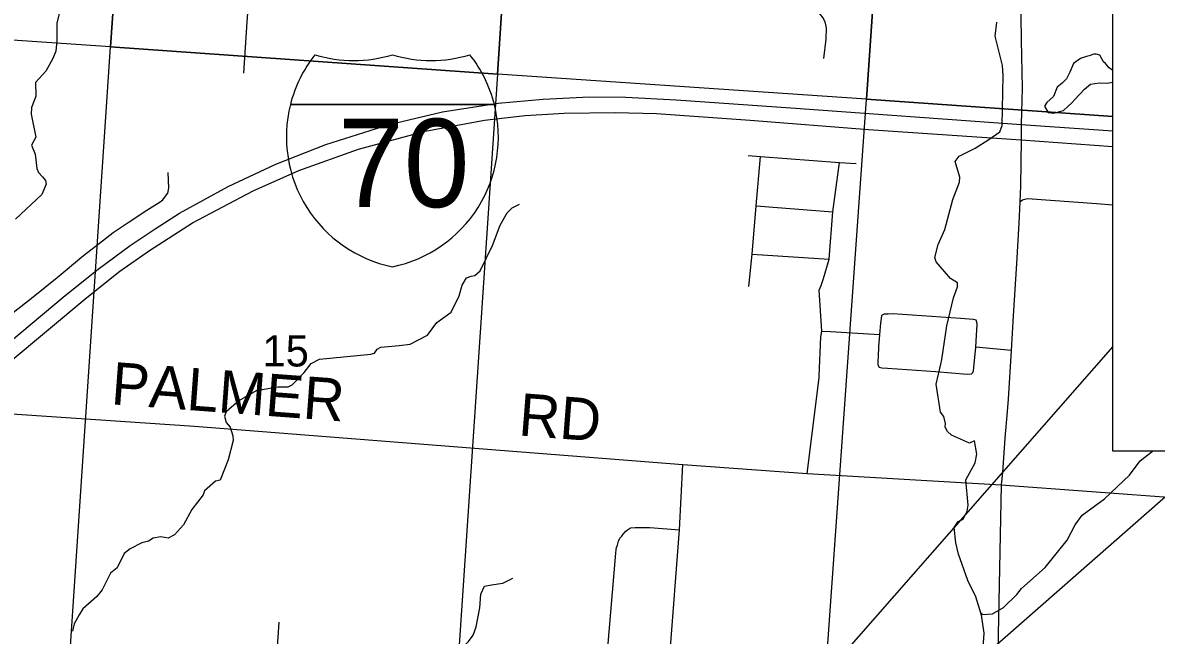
# Model space of a CAD drawing. Extents: x 0 to 34, y 0 to 26.1.
# Drawn here: x 26.701 to 28.22, y 18.306 to 19.127 of the extents above; entities that cross this region are included whole.
import ezdxf

# ---------------------------------------------------------------- set-up
doc = ezdxf.new("R2010")
doc.units = 0
for name, color, linetype in [('GM_X_County_Road', 7, 'Continuous'), ('GM_X_Interstate_Location', 7, 'Continuous'), ('GM_X_Interstate_Route', 7, 'Continuous'), ('GM_X_Interstate_Shield', 7, 'Continuous'), ('GM_X_Minor_Lake', 7, 'Continuous'), ('GM_X_Minor_River', 7, 'Continuous'), ('GM_X_Section', 7, 'Continuous'), ('GM_X_Section_Text', 7, 'Continuous'), ('GM_X_Township_Road', 7, 'Continuous'), ('GM_X_Township_Road_Text', 7, 'Continuous'), ('SH_Data', 7, 'Continuous')]:
    doc.layers.add(name, color=color, linetype=linetype)

msp = doc.modelspace()

# ---------------------------------------------------------------- linework, layer by layer
at = {"layer": 'GM_X_County_Road'}
msp.add_lwpolyline([(28.0379, 19.1672), (28.039, 19.1041), (28.04, 19.0396), (28.0393, 19.0073), (28.039, 18.9911), (28.0387, 18.9702), (28.0381, 18.9086), (28.0369, 18.8875), (28.0355, 18.8587), (28.0324, 18.8049), (28.0282, 18.7345), (28.0256, 18.6883), (28.0213, 18.6229), (28.0202, 18.6064), (28.0168, 18.5705), (28.0138, 18.5247), (28.012, 18.5079), (28.0088, 18.3512), (28.0081, 18.3077), (28.006, 18.1843)], dxfattribs=at)
at = {"layer": 'GM_X_Interstate_Route'}
for points in [[(26.6523, 18.6739), (26.7577, 18.7617), (26.8019, 18.797), (26.845, 18.8286), (26.8783, 18.8511), (26.9112, 18.8722), (26.9763, 18.9079), (27.04, 18.9379), (27.1069, 18.9642), (27.1921, 18.9909), (27.2635, 19.0078), (27.3378, 19.0196), (27.3983, 19.0251), (27.4603, 19.028), (27.5089, 19.0275), (27.5764, 19.0238), (27.73, 19.0131), (28.039, 18.9911), (28.1615, 18.9826)], [(26.6813, 18.6713), (26.7867, 18.7592), (26.831, 18.7945), (26.8709, 18.8223), (26.9285, 18.8591), (27.0096, 18.9021), (27.0709, 18.9294), (27.1509, 18.9579), (27.2403, 18.9818), (27.3196, 18.9967), (27.3741, 19.0031), (27.4263, 19.0063), (27.4946, 19.0072), (27.5501, 19.0057), (27.6755, 18.9966), (27.8342, 18.9844), (28.0387, 18.9702), (28.1615, 18.9616)]]:
    msp.add_lwpolyline(points, dxfattribs=at)
at = {"layer": 'GM_X_Interstate_Shield'}
for p, q in [((27.0596, 19.0178), (27.3329, 19.0178)), ((27.3329, 19.0178), (27.0596, 19.0178)), ((27.3329, 19.0178), (27.0596, 19.0178))]:
    msp.add_line(p, q, dxfattribs=at)
for centre, start, end in [((27.2318, 18.9743), 141.669, 165.8066), ((27.1444, 19.2542), 253.0091, 286.9909), ((27.2481, 19.2542), 253.0091, 286.9909), ((27.1607, 18.9743), 14.1934, 38.331), ((27.2318, 18.9743), 165.8066, 258.463), ((27.1607, 18.9743), 281.537, 14.1934)]:
    msp.add_arc(centre, 0.1776, start, end, dxfattribs=at)
at = {"layer": 'GM_X_Minor_Lake'}
for points in [[(28.1615, 19.0631), (28.1566, 19.0671), (28.1516, 19.0725), (28.149, 19.0751), (28.1441, 19.0839), (28.1392, 19.0854), (28.1361, 19.085), (28.1297, 19.0828), (28.1263, 19.082), (28.1183, 19.0794), (28.1089, 19.0729), (28.1039, 19.0612), (28.0997, 19.0521), (28.0937, 19.0464), (28.0872, 19.0411), (28.0819, 19.0286), (28.0732, 19.0203), (28.0701, 19.0157)], [(28.0701, 19.0157), (28.075, 19.007), (28.0826, 19.0062), (28.0887, 19.0077), (28.0955, 19.0096), (28.1015, 19.0149), (28.1069, 19.0198), (28.1107, 19.0244), (28.1236, 19.0384), (28.1315, 19.0448), (28.1433, 19.0467), (28.1535, 19.0463), (28.1615, 19.0478)]]:
    msp.add_lwpolyline(points, dxfattribs=at)
at = {"layer": 'GM_X_Minor_River'}
for points in [[(26.7504, 19.1411), (26.7466, 19.1271), (26.7466, 19.1032), (26.7451, 19.0892), (26.7413, 19.0793), (26.7318, 19.0622), (26.7182, 19.0471), (26.7185, 19.0288), (26.7166, 19.0239), (26.7125, 19.0137), (26.7121, 19.0049), (26.7185, 18.9738), (26.7128, 18.9632), (26.7177, 18.9514), (26.7199, 18.9321), (26.7222, 18.9268), (26.7275, 18.9207), (26.7316, 18.9157), (26.7324, 18.9108), (26.7267, 18.8971), (26.6911, 18.8642)], [(27.9833, 18.2273), (27.9891, 18.3093), (27.9858, 18.3336), (27.9779, 18.358), (27.9673, 18.38), (27.9549, 18.415), (27.9511, 18.4302), (27.9489, 18.4511), (27.9542, 18.459), (27.9611, 18.462), (27.9664, 18.4727), (27.9679, 18.481), (27.9646, 18.5148), (27.9771, 18.5376), (27.9794, 18.5493), (27.9764, 18.5672), (27.9696, 18.5638), (27.9454, 18.5748), (27.9401, 18.5794), (27.9371, 18.5855), (27.9375, 18.5904), (27.9352, 18.5995), (27.9307, 18.6056), (27.9251, 18.6428), (27.9312, 18.6698), (27.9327, 18.6762), (27.9392, 18.721), (27.948, 18.7586), (27.9537, 18.7734), (27.9534, 18.7787), (27.9443, 18.7844), (27.9247, 18.8069), (27.9232, 18.8126), (27.9274, 18.83), (27.9365, 18.8501), (27.9453, 18.8839), (27.9472, 18.8903), (27.9563, 18.9135), (27.9567, 18.9203), (27.9503, 18.9412), (27.9556, 18.9484), (27.9772, 18.9594), (27.9954, 18.9707), (28.0102, 18.9813), (28.0133, 18.9896), (28.0145, 19.0565), (28.0138, 19.0701), (28.004, 19.1093), (28.006, 19.1282)], [(26.9908, 18.621), (27.014, 18.6346), (27.0428, 18.6395), (27.0568, 18.6395), (27.0621, 18.6421), (27.078, 18.6584), (27.0875, 18.6706), (27.0985, 18.6766), (27.1674, 18.6833), (27.1724, 18.6844), (27.1758, 18.6901), (27.1807, 18.6924), (27.2053, 18.6946), (27.2201, 18.6965), (27.2432, 18.7085), (27.2557, 18.7256), (27.2751, 18.7396), (27.2857, 18.7612), (27.2899, 18.7756), (27.2956, 18.7855), (27.3017, 18.7878), (27.3066, 18.7885), (27.3138, 18.795), (27.3306, 18.8287), (27.3405, 18.856), (27.35, 18.8727), (27.3568, 18.8791), (27.3666, 18.884)], [(26.9908, 18.621), (26.9733, 18.6057), (26.9714, 18.6), (26.9737, 18.5917), (26.979, 18.5852), (26.9824, 18.5738), (26.9828, 18.5674), (26.9763, 18.5416), (26.9653, 18.5143), (26.9592, 18.5131), (26.9445, 18.4999), (26.9426, 18.4945), (26.9274, 18.4752), (26.9164, 18.4543), (26.9043, 18.4411), (26.8956, 18.4365), (26.8861, 18.4384), (26.8759, 18.4366), (26.8695, 18.4328), (26.8604, 18.4305), (26.8449, 18.4222), (26.8369, 18.4161), (26.8274, 18.3968), (26.8183, 18.3899), (26.8073, 18.3675), (26.8001, 18.3584), (26.7816, 18.3421), (26.7766, 18.3338), (26.7698, 18.322), (26.7675, 18.3118)], [(27.985, 18.336), (27.9865, 18.3344), (28.0002, 18.3351), (28.015, 18.3438), (28.0332, 18.3613), (28.0393, 18.3692), (28.0711, 18.3972), (28.1004, 18.434), (28.111, 18.4545), (28.1205, 18.4674), (28.1505, 18.4893), (28.1838, 18.5211), (28.1983, 18.5401), (28.2147, 18.5533)], [(27.1008, 18.0678), (27.1268, 18.0861), (27.145, 18.0959), (27.159, 18.1069), (27.1647, 18.1088), (27.1882, 18.127), (27.2087, 18.1471), (27.219, 18.1618), (27.2213, 18.1698), (27.2293, 18.2123), (27.2403, 18.2275), (27.2506, 18.2461), (27.2737, 18.2737), (27.2984, 18.298), (27.3045, 18.3067), (27.3087, 18.3177), (27.3133, 18.3431), (27.3148, 18.3614), (27.3198, 18.3724), (27.3292, 18.3739), (27.3444, 18.3761), (27.3577, 18.3829)], [(26.9895, 18.1362), (26.9978, 18.1388), (27.0308, 18.1729), (27.0357, 18.1797), (27.0369, 18.1907), (27.0362, 18.2162), (27.0412, 18.2363), (27.0439, 18.2587), (27.042, 18.2841), (27.0444, 18.324)]]:
    msp.add_lwpolyline(points, dxfattribs=at)
at = {"layer": 'GM_X_Section'}
for points in [[(26.3915, 20.1255), (26.8884, 20.0918), (26.8184, 19.0949), (26.3256, 19.1287)], [(26.8884, 20.0918), (27.4021, 20.0547), (27.3369, 19.0584), (26.8184, 19.0949)], [(27.4021, 20.0547), (27.9001, 20.0205), (27.8314, 19.025), (27.3369, 19.0584)], [(26.8184, 19.0949), (27.3369, 19.0584), (27.2703, 18.0605), (26.7521, 18.098)]]:
    msp.add_lwpolyline(points, close=True, dxfattribs=at)
for points in [[(28.1615, 19.0015), (27.8314, 19.025), (27.9001, 20.0205), (28.4191, 19.9828), (28.3774, 19.3933)], [(28.3147, 18.5533), (28.2704, 17.9878), (27.7604, 18.0248), (27.8314, 19.025), (28.1615, 19.0015)]]:
    msp.add_lwpolyline(points, dxfattribs=at)
at = {"layer": 'GM_X_Township_Road'}
for p, q in [((27.6837, 18.8818), (27.7866, 18.8739)), ((27.6783, 18.8172), (27.7815, 18.8104)), ((28.012, 18.5079), (29.3107, 18.4123))]:
    msp.add_line(p, q, dxfattribs=at)
for points in [[(26.9974, 19.0598), (27.0015, 19.1287), (27.0053, 19.1757), (27.0082, 19.2146), (27.0084, 19.2231), (27.0064, 19.2319), (27, 19.2448), (26.9938, 19.2546), (26.9833, 19.2705), (26.9765, 19.2805), (26.9715, 19.2901), (26.9688, 19.297), (26.9659, 19.3103), (26.965, 19.3189), (26.9654, 19.3353), (26.9658, 19.3432)], [(27.7744, 19.0792), (27.7775, 19.1052), (27.778, 19.1207), (27.7763, 19.1283), (27.7729, 19.1342), (27.7633, 19.1468)], [(27.6731, 18.9493), (27.6895, 18.9479), (27.7952, 18.9402), (27.8177, 18.9386)], [(27.6739, 18.7739), (27.6783, 18.8172), (27.6837, 18.8818), (27.6895, 18.9479)], [(27.7682, 18.6536), (27.7703, 18.7062), (27.7715, 18.7138), (27.7681, 18.7689), (27.7707, 18.775), (27.7737, 18.7845), (27.7815, 18.8104), (27.7866, 18.8739), (27.7952, 18.9402)], [(26.6879, 18.7392), (26.7151, 18.7598), (26.7472, 18.7859), (26.7824, 18.8155), (26.8076, 18.8349), (26.8221, 18.8461), (26.8423, 18.8595), (26.8672, 18.8763), (26.8851, 18.8874), (26.8885, 18.89), (26.8924, 18.8949), (26.8954, 18.899), (26.8967, 18.9055), (26.8958, 18.9268)], [(28.0369, 18.8875), (28.0406, 18.89), (28.0435, 18.8911), (28.0474, 18.8916), (28.1398, 18.8851), (28.1615, 18.8832)], [(28.0256, 18.6883), (27.9779, 18.6926), (27.9789, 18.7083), (27.9797, 18.7228), (27.9794, 18.726), (27.9783, 18.7286), (27.9751, 18.7297), (27.9574, 18.7308), (27.8668, 18.7371), (27.8607, 18.7368), (27.8553, 18.7368), (27.8517, 18.7351), (27.851, 18.7308), (27.8505, 18.7247), (27.8488, 18.7094), (27.8476, 18.6929), (27.8471, 18.6802), (27.8468, 18.6739), (27.8466, 18.6691), (27.8485, 18.6659), (27.8522, 18.6649), (27.8597, 18.6644), (27.9246, 18.6598), (27.9665, 18.6566), (27.9722, 18.6568), (27.9741, 18.6586), (27.9749, 18.6609), (27.9753, 18.6655), (27.9779, 18.6926)], [(27.7715, 18.7138), (27.7834, 18.7135), (27.8488, 18.7094)], [(25.7935, 18.6656), (26.0437, 18.6467), (26.0794, 18.644), (26.1683, 18.637), (26.1959, 18.6353), (26.3393, 18.6245), (26.5433, 18.613), (26.5759, 18.6102), (26.6049, 18.6077), (26.6331, 18.6069), (26.9312, 18.5865), (27.5853, 18.5352), (27.752, 18.5234), (28.012, 18.5079)], [(27.752, 18.5234), (27.7681, 18.6516), (27.7682, 18.6536)], [(27.5682, 18.2788), (27.5808, 18.4478), (27.5853, 18.5352)], [(27.4691, 18.046), (27.4749, 18.1664), (27.4847, 18.2849), (27.4955, 18.4167), (27.4963, 18.4209), (27.4966, 18.4239), (27.4977, 18.4273), (27.4992, 18.4326), (27.5011, 18.4365), (27.5038, 18.4395), (27.5057, 18.4418), (27.5087, 18.4456), (27.5113, 18.4479), (27.5155, 18.4506), (27.5216, 18.451), (27.5254, 18.451), (27.5303, 18.451), (27.5413, 18.4507), (27.5808, 18.4478)]]:
    msp.add_lwpolyline(points, dxfattribs=at)
at = {"layer": 'SH_Data'}
for points in [[(28.1615, 19.3933), (29.8402, 19.3933), (29.8402, 18.5533), (28.1615, 18.5533)], [(28.1615, 18.6933), (27.1615, 17.5533), (28.3015, 18.5533), (28.1615, 18.5533)]]:
    msp.add_lwpolyline(points, close=True, dxfattribs=at)

# ---------------------------------------------------------------- texts
at = {"layer": 'GM_X_Interstate_Location'}
for s in ['-', '.', ',']:
    msp.add_text(s, height=0.000189, dxfattribs=at).set_placement((27.1962, 18.9423))
msp.add_text('70', height=0.000189, rotation=0, dxfattribs=at).set_placement((27.1575, 18.9031))
at = {"layer": 'GM_X_Interstate_Shield'}
msp.add_text('70', height=0.11837, dxfattribs=at).set_placement((27.1235, 18.8802))
at = {"layer": 'GM_X_Section_Text'}
msp.add_text('15', height=0.04186, rotation=0, dxfattribs=at).set_placement((27.0221, 18.6667))
at = {"layer": 'GM_X_Township_Road_Text'}
for s, rotation, p in [('PALMER', 355.7569, (26.8183, 18.6161)), ('RD', 355.5623, (27.3642, 18.5744))]:
    msp.add_text(s, height=0.05682, rotation=rotation, dxfattribs=at).set_placement(p)

doc.saveas('drawing.dxf')
